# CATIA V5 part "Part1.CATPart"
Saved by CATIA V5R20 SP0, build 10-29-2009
Part number: Part1
Material "White": density 7860 kg/m3, Young's modulus 2e+11 Pa, Poisson ratio 0.266
Bounding box of the stored display mesh (mm): x -140 to 200, y -30 to 30, z -32.962 to 52
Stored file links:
  C:\Users\12584\Desktop\新建文件夹 (3)\Part1.CATPart
  D:\B20\win_b64\startup\materials\Catalog.CATMaterial
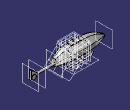
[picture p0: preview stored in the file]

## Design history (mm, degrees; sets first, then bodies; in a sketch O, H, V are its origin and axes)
Body1 (main body), material "White"
  Plane1: type Offset, RefPlane yz-plane, Offset 40
  Plane2: type Offset, RefPlane yz-plane, Offset 40, reversed
  Sketch1 on Plane2, origin (-40, 0, 0), H (0, 1, 0), V (0, 0, 1)
    point P1 (-30, 0)
    line L1 (-30, 0) -> (-30, 20)
    line L2 (-30, 20) -> (-10, 40)
    line L3 (-10, 40) -> (10, 40)
    line L4 (10, 40) -> (30, 20)
    line L5 (30, 20) -> (30, 0)
    point P6 (30, 0)
    line L6 (30, 0) -> (10, -20)
    line L7 (10, -20) -> (-10, -20)
    line L8 (-10, -20) -> (-30, 0)
    coincidence: P1 H, P6 H
    vertical: L1 V, L5 V
    horizontal: L3 H, L7 H
    perpendicularity: L4 L2
    parallelism: L8 L4
  Sketch2 on Plane1, origin (40, 0, 0), H (0, 1, 0), V (0, 0, 1)
    line L1 (-30, 20) -> (-10, 40)
    line L2 (-10, 40) -> (10, 40)
    line L3 (10, 40) -> (30, 20)
    line L4 (30, 20) -> (30, 0)
    line L5 (30, 0) -> (10, -20)
    line L6 (10, -20) -> (-10, -20)
    line L7 (-10, -20) -> (-30, 0)
    line L8 (-30, 0) -> (-30, 20)
    horizontal: L2 H, L6 H
    vertical: L4 V, L8 V
    parallelism: L5 L1
  Loft1: solid, Sections (Sketch1; Sketch2)
  Plane3: type Offset, RefPlane Plane1, Offset 50
  Sketch3 on Plane3, origin (90, 0, 0), H (0, 1, 0), V (0, 0, 1)
    point P1 (-5, -10)
    line L1 (-5, -10) -> (5, -10)
    line L2 (5, -10) -> (15, 0)
    line L3 (15, 0) -> (15, 10)
    line L4 (15, 10) -> (5, 20)
    line L5 (5, 20) -> (-5, 20)
    line L6 (-5, 20) -> (-15, 10)
    line L7 (-15, 10) -> (-15, 0)
    line L8 (-15, 0) -> (-5, -10)
    distance P1 V = 5
    distance P1 H = 10
    length L1 = 10
    length L5 = 10
    horizontal: L1 H, L5 H
    vertical: L3 V, L7 V
    perpendicularity: L4 L2
    parallelism: L6 L2
  Point1: type OnPlane, Support face of Loft1, H -30, V 0, Direction (0, 1, 0)
  Point2: type OnCurve, Support Sketch3, RefPoint vertex [element of Sketch3 | element of Sketch3], Length 82.4264
  Sketch4 on Plane1, origin (40, 0, 0), H (0, 1, 0), V (0, 0, 1)
    line L1 (-10, -20) -> (-30, 0)
    point P2 (-30, 0)
    line L2 (-30, 0) -> (-30, 20)
    line L3 (-30, 20) -> (-10, 40)
    line L4 (-10, 40) -> (10, 40)
    line L5 (10, 40) -> (30, 20)
    line L6 (30, 20) -> (30, 0)
    line L7 (30, 0) -> (10, -20)
    line L8 (10, -20) -> (-10, -20)
    coincidence: P2 H
    vertical: L2 V, L6 V
    perpendicularity: L3 L1
    horizontal: L4 H, L8 H
    parallelism: L5 L1
  Loft2: solid, Sections (Sketch4; Sketch3)
  Sketch5 on Plane3, origin (90, 0, 0), H (0, 1, 0), V (0, 0, 1)
    circle A1 centre (0, 0) radius 5
    radius A1 = 5
  Pad1: profile Sketch5, direction (1, 0, 0), length 100
  Plane4: type Offset, RefPlane Plane3, Offset 80
  Sketch6 on Plane4, origin (170, 0, 0), H (0, 1, 0), V (0, 0, 1)
    point P1 (-5, -5)
    line L1 (-5, -5) -> (5, -5)
    line L2 (5, -5) -> (5, 5)
    line L3 (5, 5) -> (-5, 5)
    line L4 (-5, 5) -> (-5, -5)
    point P2 (5, -5)
    length L3 = 10
    length L4 = 10
    distance P1 V = 5
    distance P2 H = 5
    horizontal: L1 H, L3 H
    vertical: L2 V, L4 V
  Plane5: type Offset, RefPlane Plane4, Offset 30
  Sketch7 on Plane5, origin (200, 0, 0), H (0, 1, 0), V (0, 0, 1)
    point P1 (-5, -10)
    line L1 (-5, -10) -> (5, -10)
    line L2 (5, -10) -> (5, 30)
    line L3 (5, 30) -> (-5, 30)
    line L4 (-5, 30) -> (-5, -10)
    length L3 = 10
    distance P1 V = 5
    horizontal: L1 H, L3 H
    vertical: L2 V, L4 V
  Loft3: solid, Sections (Sketch6; Sketch7)
  Plane6: type Offset, RefPlane Plane2, Offset 100, reversed
  Sketch8 on Plane6, origin (-140, 0, 0), H (0, 1, 0), V (0, 0, 1)
    point P1 (-1.624, 3.8756)
    line L1 (-1.624, 3.8756) -> (1.6241, 3.8756)
    line L2 (1.6241, 3.8756) -> (3.7895, 1.5369)
    line L3 (3.7895, 1.5369) -> (3.7895, -1.5214)
    line L4 (3.7895, -1.5214) -> (1.6241, -3.5264)
    line L5 (1.6241, -3.5264) -> (-1.624, -3.5264)
    line L6 (-1.624, -3.5264) -> (-3.4804, -1.5214)
    line L7 (-3.4804, -1.5214) -> (-3.4804, 1.5369)
    line L8 (-3.4804, 1.5369) -> (-1.624, 3.8756)
    length L1 = 3.2481
    distance P1 V = 1.624
    horizontal: L1 H, L5 H
    vertical: L3 V, L7 V
    perpendicularity: L4 L2
    parallelism: L6 L2
  Loft4: solid, Sections (Sketch8; {boundary Boundary {extract ExtractElem face of Loft1}}), EndFace face of Loft1
  Plane7: type Offset, RefPlane xy-plane, Offset 40
  Sketch9 on Plane7, origin (0, 0, 40), H (1, 0, 0), V (0, 1, 0)
    line L1 (-20.7197, 10.4586) -> (20.3734, 10.4586)
    line L2 (20.3734, 10.4586) -> (20.3734, -10.3977)
    line L3 (20.3734, -10.3977) -> (-20.7197, -10.3977)
    line L4 (-20.7197, -10.3977) -> (-20.7197, 10.4586)
    horizontal: L1 H, L3 H
    vertical: L2 V, L4 V
  Pad2: profile Sketch9, direction (0, 0, 1), length 5
  Plane8: type Offset, RefPlane Plane7, Offset 5
  Sketch10 on Plane8, origin (0, 0, 45), H (1, 0, 0), V (0, 1, 0)
    circle A1 centre (0, 0) radius 4.7227
  Pad3: profile Sketch10, direction (0, 0, 1), length 7
  Plane9: type Offset, RefPlane zx-plane, Offset 30
  Plane10: type Offset, RefPlane zx-plane, Offset 30, reversed
  Plane11: type Offset, RefPlane Plane1, Offset 20, reversed
  Plane12: type Offset, RefPlane Plane2, Offset 20
  Sketch11 on Plane11, origin (20, 0, 0), H (0, 1, 0), V (0, 0, 1)
    line L1 (20, 0) -> (20, -30)
    point P2 (20, -30)
    vertical: L1 V
  Plane13: type Normal, Curve Sketch11, RefPoint Sketch11.P2
  Sketch12 on Plane13, origin (0, 0, -30), H (1, 0, 0), V (0, -1, 0)
    circle A1 centre (20, -20) radius 2.5
    radius A1 = 2.5
  Rib1: profile Sketch12, centre curve Sketch11
  Sketch13 on Plane11, origin (20, 0, 0), H (0, 1, 0), V (0, 0, 1)
    line L1 (-20, 0) -> (-20, -30)
    point P2 (-20, -30)
    vertical: L1 V
  Plane14: type Normal, Curve Sketch13, RefPoint Sketch13.P2
  Sketch14 on Plane14, origin (0, 0, -30), H (1, 0, 0), V (0, -1, 0)
    circle A1 centre (20, 20) radius 2.5
    radius A1 = 2.5
  Rib2: profile Sketch14, centre curve Sketch13
  Sketch15 on Plane12, origin (-20, 0, 0), H (0, 1, 0), V (0, 0, 1)
    line L1 (20, 0) -> (20, -30)
    point P1 (20, 0)
    point P2 (20, -30)
    coincidence: P1 H
    vertical: L1 V
  Plane15: type Normal, Curve Sketch15, RefPoint Sketch15.P2
  Sketch16 on Plane15, origin (0, 0, -30), H (1, 0, 0), V (0, -1, 0)
    circle A1 centre (-20, -20) radius 2.5
    radius A1 = 2.5
  Rib3: profile Sketch16, centre curve Sketch15
  Sketch17 on Plane12, origin (-20, 0, 0), H (0, 1, 0), V (0, 0, 1)
    line L1 (-20, 0) -> (-20, -30)
    point P1 (-20, 0)
    point P2 (-20, -30)
    coincidence: P1 H
    vertical: L1 V
  Plane16: type Normal, Curve Sketch17, RefPoint Sketch17.P2
  Sketch18 on Plane16, origin (0, 0, -30), H (1, 0, 0), V (0, -1, 0)
    circle A1 centre (-20, 20) radius 2.5
    radius A1 = 2.5
  Rib4: profile Sketch18, centre curve Sketch17
  Plane17: type Offset, RefPlane Plane10, Offset 10
  Sketch19 on Plane17, origin (0, -20, 0), H (-1, 0, 0), V (0, 0, 1)
    point P1 (-50, -20)
    line L1 (-50, -20) -> (-40, -30)
    line L2 (-40, -30) -> (60, -30)
    line L3 (60, -30) -> (70, -20)
    horizontal: L2 H
  Plane18: type Normal, Curve Sketch19, RefPoint Sketch19.P1
  Sketch20 on Plane18, origin (15, 0, 15), H (0, -1, 0), V (-0.7071, 0, 0.7071)
    circle A1 centre (20, -50) radius 2.5
    radius A1 = 2.5
  Rib5: profile Sketch20, centre curve Sketch19
  Plane19: type Offset, RefPlane Plane9, Offset 10, reversed
  Sketch21 on Plane19, origin (0, 20, 0), H (-1, 0, 0), V (0, 0, 1)
    point P1 (-50, -20)
    line L1 (-50, -20) -> (-40, -30)
    line L2 (-40, -30) -> (60, -30)
    line L3 (60, -30) -> (70, -20)
    horizontal: L2 H
    perpendicularity: L3 L1
  Plane20: type Normal, Curve Sketch21, RefPoint Sketch21.P1
  Sketch22 on Plane20, origin (15, 0, 15), H (0, -1, 0), V (-0.7071, 0, 0.7071)
    circle A1 centre (-20, -50) radius 2.5
    radius A1 = 2.5
  Rib6: profile Sketch22, centre curve Sketch21
  Sketch23 on zx-plane, origin (0, 0, 0), H (-1, 0, 0), V (0, 0, 1)
    circle A1 centre (-190, 0) radius 10
  Pad4: profile Sketch23, direction (0, 1, 0), length 7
